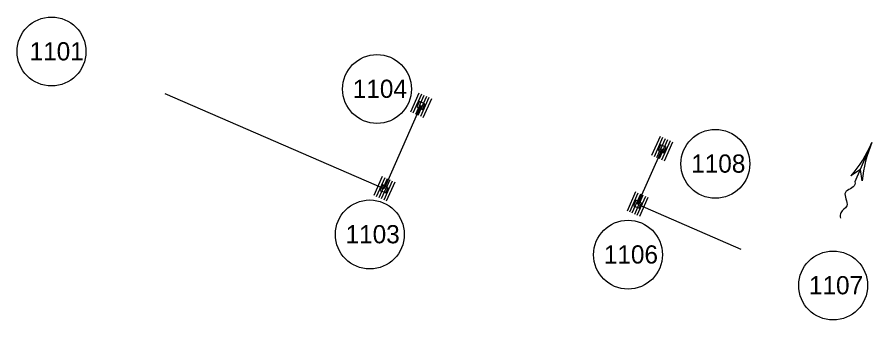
# Model space of a CAD drawing. Extents: x 594534 to 598564, y 225861 to 236229.
# Drawn here: x 594766.5 to 595048.4, y 228573.9 to 228673.7 of the extents above; entities that cross this region are included whole.
import ezdxf

# ---------------------------------------------------------------- set-up
doc = ezdxf.new("R2010")
doc.units = 0
for name, color, linetype in [('P_DRN_Flow', 7, 'Continuous'), ('P_DRN_Inlet', 7, 'Continuous'), ('P_DRN_SS_UG', 7, 'Continuous'), ('P_DRN_Text', 7, 'Continuous')]:
    doc.layers.add(name, color=color, linetype=linetype)

msp = doc.modelspace()

# ---------------------------------------------------------------- linework, layer by layer
at = {"layer": 'P_DRN_Flow'}
msp.add_line((595048.44, 228632.33), (595042.85, 228619.35), dxfattribs=at)
msp.add_lwpolyline([(595045.22, 228619.78), (595044.65, 228623.51), (595041.54, 228621.36)], dxfattribs=at)
for centre, start, end in [((595009.89, 228648.9), 318.9689, 336.7313), ((595086.98, 228615.75), 156.7313, 174.4936)]:
    msp.add_arc(centre, 41.96, start, end, dxfattribs=at)
msp.add_spline([(595042.85, 228619.35), (595042.83, 228618.5), (595039.68, 228615.93), (595040.14, 228611.46), (595038.16, 228609.23), (595038.06, 228607.4)], degree=3, dxfattribs=at)
at = {"layer": 'P_DRN_Inlet'}
for p, q in [((594899.03, 228648.65), (594896.24, 228642.37)), ((594899.86, 228648.28), (594897.06, 228642)), ((594900.68, 228647.92), (594897.88, 228641.64)), ((594901.5, 228647.55), (594898.7, 228641.27)), ((594902.32, 228647.19), (594899.53, 228640.91)), ((594903.14, 228646.82), (594900.35, 228640.54)), ((594978.57, 228634.34), (594975.78, 228628.06)), ((594979.4, 228633.97), (594976.6, 228627.69)), ((594980.22, 228633.61), (594977.42, 228627.33)), ((594981.04, 228633.24), (594978.24, 228626.96)), ((594981.86, 228632.87), (594979.07, 228626.59)), ((594982.69, 228632.51), (594979.89, 228626.23)), ((594886.95, 228621.13), (594884.16, 228614.85)), ((594887.78, 228620.76), (594884.98, 228614.48)), ((594888.6, 228620.4), (594885.8, 228614.12)), ((594889.42, 228620.03), (594886.62, 228613.75)), ((594890.24, 228619.67), (594887.45, 228613.39)), ((594891.06, 228619.3), (594888.27, 228613.02)), ((594970.45, 228616.05), (594967.66, 228609.77)), ((594971.27, 228615.69), (594968.48, 228609.41)), ((594972.1, 228615.32), (594969.3, 228609.04)), ((594972.92, 228614.96), (594970.12, 228608.68)), ((594973.74, 228614.59), (594970.94, 228608.31)), ((594974.56, 228614.22), (594971.77, 228607.94))]:
    msp.add_line(p, q, dxfattribs=at)
for points in [[(594899.18, 228645.92), (594898.37, 228644.09), (594900.2, 228643.27), (594901.01, 228645.1)], [(594978.72, 228631.6), (594977.91, 228629.78), (594979.74, 228628.96), (594980.55, 228630.79)], [(594887.1, 228618.4), (594886.29, 228616.57), (594888.12, 228615.76), (594888.93, 228617.58)], [(594970.6, 228613.32), (594969.79, 228611.49), (594971.62, 228610.68), (594972.43, 228612.5)]]:
    msp.add_lwpolyline(points, close=True, dxfattribs=at)
at = {"layer": 'P_DRN_SS_UG'}
for p, q in [((594887.61, 228617.08), (594815.29, 228648.45)), ((594899.69, 228644.59), (594887.61, 228617.08)), ((594979.23, 228630.28), (594971.11, 228612)), ((594971.11, 228612), (595005.25, 228597.22))]:
    msp.add_line(p, q, dxfattribs=at)
at = {"layer": 'P_DRN_Text'}
for centre in [(594777.85, 228662.37), (594885.19, 228650.01), (594996.81, 228625.33), (594882.83, 228602.05), (594968, 228595.38), (595035.65, 228585.23)]:
    msp.add_circle(centre, 11.36, dxfattribs=at)

# ---------------------------------------------------------------- texts
for s, p in [('1101', (594770.63, 228659.45)), ('1104', (594877.22, 228647.09)), ('1108', (594988.84, 228622.42)), ('1103', (594874.85, 228599.13)), ('1106', (594960.03, 228592.46)), ('1107', (595027.68, 228582.31))]:
    msp.add_text(s, height=6, dxfattribs=at).set_placement(p)

doc.saveas('drawing.dxf')
